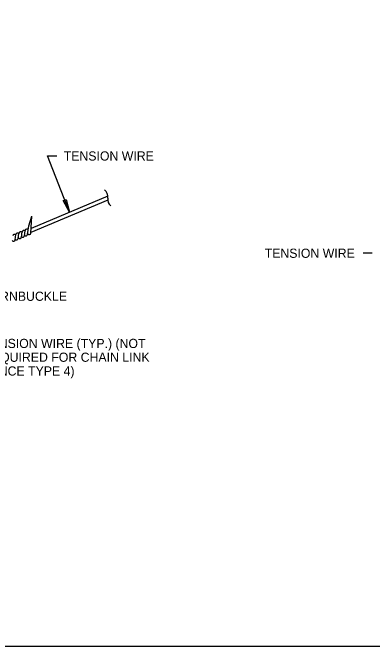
# Model space of a CAD drawing. Extents: x 99862 to 104211, y 98939 to 105076.
# Drawn here: x 100816 to 101442, y 103000 to 104103 of the extents above; entities that cross this region are included whole.
import ezdxf

# ---------------------------------------------------------------- set-up
doc = ezdxf.new("R2010")
doc.units = 0
for name, color, linetype in [('Level 1', 7, 'Continuous'), ('Level 15', 7, 'Continuous'), ('Level 2', 7, 'Continuous'), ('Level 20', 7, 'Continuous')]:
    doc.layers.add(name, color=color, linetype=linetype)

msp = doc.modelspace()

# ---------------------------------------------------------------- linework, layer by layer
at = {"layer": 'Level 1'}
msp.add_lwpolyline([(99862, 102999.5), (103151, 102999.5), (103151, 105075.5), (99862, 105075.5)], close=True, dxfattribs=at)
at = {"layer": 'Level 15'}
for p, q in [((100877, 103853.6), (100893, 103853.6)), ((100914.9, 103755.6), (100877, 103853.6)), ((101442.2, 103684.2), (101426.2, 103684.2))]:
    msp.add_line(p, q, dxfattribs=at)
msp.add_lwpolyline([(100914.9, 103755.6), (100903.9, 103775.8), (100907.1, 103775.9), (100909.5, 103777.9)], close=True, dxfattribs=at)
at = {"layer": 'Level 2'}
for p, q in [((100981.6, 103776.9), (100847.8, 103720.3)), ((100981.6, 103783.8), (100848.3, 103727.3)), ((100844, 103732.1), (100849.6, 103748.7)), ((100847.8, 103719.4), (100849.6, 103748.7)), ((100842.1, 103716.6), (100844, 103732.1)), ((100825.8, 103709.5), (100827, 103719.2)), ((100831.2, 103711.8), (100832.6, 103721.9)), ((100836.6, 103714.2), (100837.9, 103723.8)), ((100820.4, 103707.3), (100821.6, 103716.9))]:
    msp.add_line(p, q, dxfattribs=at)
for centre, radius, start, end in [((100966.4, 103782.4), 15.4, 352.3442, 52.3442), ((100996.8, 103778.3), 15.4, 172.3442, 229.3377), ((100824.5, 103716.4), 2.95, 35.0627, 175.5196), ((100830, 103718.8), 2.95, 35.9637, 172.7588), ((100835.4, 103721.1), 2.95, 36.5865, 180.1158), ((100840.8, 103723.4), 2.95, 37.9847, 172.649), ((100844.8, 103719.6), 2.95, 209.6896, 356.5283), ((100817.5, 103707.9), 2.95, 216.1935, 356.7986), ((100819.1, 103714.1), 2.95, 36.1359, 173.2631), ((100822.9, 103710.2), 2.95, 216.1359, 358.8543), ((100828.4, 103712.5), 2.95, 216.0039, 0.1158), ((100833.8, 103714.9), 2.95, 215.8843, 359.324), ((100839.2, 103717.2), 2.95, 215.9631, 357.5858)]:
    msp.add_arc(centre, radius, start, end, dxfattribs=at)

# ---------------------------------------------------------------- texts
at = {"layer": 'Level 20'}
for s, p in [('TENSION WIRE', (100905, 103845.6)), ('TURNBUCKLE', (100765.7, 103601.3)), ('TENSION WIRE (TYP.) (NOT', (100764.5, 103519.1)), ('REQUIRED FOR CHAIN LINK', (100764.5, 103495.1)), ('FENCE TYPE 4)', (100764.5, 103471.1))]:
    msp.add_text(s, height=16, dxfattribs=at).set_placement(p)
msp.add_text('TENSION WIRE', height=16, rotation=360, dxfattribs=at).set_placement((101254.8, 103676.2))

doc.saveas('drawing.dxf')
